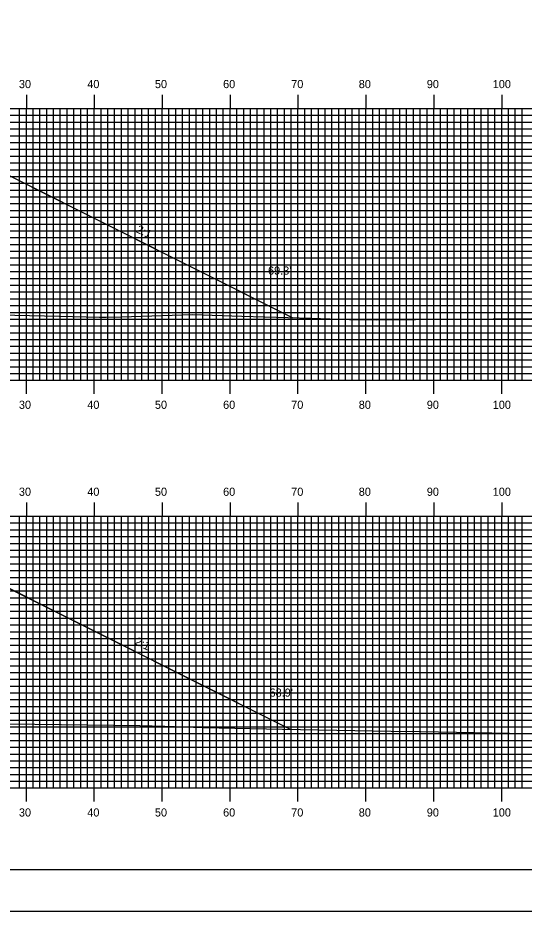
# Model space of a CAD drawing. Extents: x 1810980 to 1811323, y 442591 to 442811.
# Drawn here: x 1811174.6 to 1811249.2, y 442590.5 to 442722 of the extents above; entities that cross this region are included whole.
import ezdxf

# ---------------------------------------------------------------- set-up
doc = ezdxf.new("R2010")
doc.units = 0
for name, color, linetype in [('ANNOTATION', 7, 'Continuous'), ('BORDER', 7, 'Continuous'), ('D_Roadway_Centerline', 7, 'Continuous'), ('D_Roadway_SlopeLines', 7, 'Continuous'), ('D_Text_Standard', 7, 'Continuous'), ('H_V ANNOTATION', 7, 'Continuous'), ('MAJOR', 7, 'Continuous'), ('MINOR', 7, 'Continuous'), ('PLOT BOUNDARY', 7, 'Continuous'), ('S_Roadway_Centerline', 7, 'Continuous')]:
    doc.layers.add(name, color=color, linetype=linetype)

msp = doc.modelspace()

# ---------------------------------------------------------------- linework, layer by layer
at = {"layer": 'BORDER'}
msp.add_lwpolyline([(1810996.29, 442596.67), (1811316.29, 442596.67), (1811316.29, 442806.67), (1810996.29, 442806.67)], close=True, dxfattribs=at)
at = {"layer": 'D_Roadway_Centerline'}
for points in [[(1811076.36, 442679.21), (1811117.68, 442699.87), (1811122.89, 442702.48), (1811125.89, 442702.54), (1811133.89, 442702.7), (1811145.89, 442702.12), (1811157.89, 442701.54), (1811165.89, 442701.16), (1811168.89, 442701.02), (1811174.42, 442698.25), (1811215.15, 442677.88)], [(1811078.22, 442619.39), (1811117.68, 442639.12), (1811122.89, 442641.73), (1811125.89, 442641.79), (1811133.89, 442641.95), (1811145.89, 442641.37), (1811157.89, 442640.79), (1811165.89, 442640.41), (1811168.89, 442640.27), (1811174.42, 442637.5), (1811214.76, 442617.33)]]:
    msp.add_lwpolyline(points, dxfattribs=at)
at = {"layer": 'D_Roadway_SlopeLines'}
for points in [[(1811168.89, 442701.02), (1811215.15, 442677.88)], [(1811168.89, 442640.27), (1811214.76, 442617.33)]]:
    msp.add_lwpolyline(points, dxfattribs=at)
at = {"layer": 'MAJOR'}
for p, q in [((1811175.89, 442710.67), (1811175.89, 442708.67)), ((1811185.89, 442710.67), (1811185.89, 442708.67)), ((1811195.89, 442710.67), (1811195.89, 442708.67)), ((1811205.89, 442710.67), (1811205.89, 442708.67)), ((1811215.89, 442710.67), (1811215.89, 442708.67)), ((1811225.89, 442710.67), (1811225.89, 442708.67)), ((1811235.89, 442710.67), (1811235.89, 442708.67)), ((1811245.89, 442710.67), (1811245.89, 442708.67)), ((1811005.89, 442708.67), (1811285.89, 442708.67)), ((1811005.89, 442708.67), (1811285.89, 442708.67)), ((1811175.89, 442668.67), (1811175.89, 442708.67)), ((1811185.89, 442668.67), (1811185.89, 442708.67)), ((1811195.89, 442668.67), (1811195.89, 442708.67)), ((1811205.89, 442668.67), (1811205.89, 442708.67)), ((1811215.89, 442668.67), (1811215.89, 442708.67)), ((1811225.89, 442668.67), (1811225.89, 442708.67)), ((1811235.89, 442668.67), (1811235.89, 442708.67)), ((1811245.89, 442668.67), (1811245.89, 442708.67)), ((1811005.89, 442703.67), (1811285.89, 442703.67)), ((1811005.89, 442698.67), (1811285.89, 442698.67)), ((1811005.89, 442693.67), (1811285.89, 442693.67)), ((1811005.89, 442688.67), (1811285.89, 442688.67)), ((1811005.89, 442683.67), (1811285.89, 442683.67)), ((1811005.89, 442678.67), (1811285.89, 442678.67)), ((1811005.89, 442673.67), (1811285.89, 442673.67)), ((1811005.89, 442668.67), (1811285.89, 442668.67)), ((1811005.89, 442668.67), (1811285.89, 442668.67)), ((1811175.89, 442666.66), (1811175.89, 442668.67)), ((1811185.89, 442666.66), (1811185.89, 442668.67)), ((1811195.89, 442666.66), (1811195.89, 442668.67)), ((1811205.89, 442666.66), (1811205.89, 442668.67)), ((1811215.89, 442666.66), (1811215.89, 442668.67)), ((1811225.89, 442666.66), (1811225.89, 442668.67)), ((1811235.89, 442666.66), (1811235.89, 442668.67)), ((1811245.89, 442666.66), (1811245.89, 442668.67)), ((1811175.89, 442650.67), (1811175.89, 442648.67)), ((1811185.89, 442650.67), (1811185.89, 442648.67)), ((1811195.89, 442650.67), (1811195.89, 442648.67)), ((1811205.89, 442650.67), (1811205.89, 442648.67)), ((1811215.89, 442650.67), (1811215.89, 442648.67)), ((1811225.89, 442650.67), (1811225.89, 442648.67)), ((1811235.89, 442650.67), (1811235.89, 442648.67)), ((1811245.89, 442650.67), (1811245.89, 442648.67)), ((1811005.89, 442648.67), (1811285.89, 442648.67)), ((1811005.89, 442648.67), (1811285.89, 442648.67)), ((1811175.89, 442608.67), (1811175.89, 442648.67)), ((1811185.89, 442608.67), (1811185.89, 442648.67)), ((1811195.89, 442608.67), (1811195.89, 442648.67)), ((1811205.89, 442608.67), (1811205.89, 442648.67)), ((1811215.89, 442608.67), (1811215.89, 442648.67)), ((1811225.89, 442608.67), (1811225.89, 442648.67)), ((1811235.89, 442608.67), (1811235.89, 442648.67)), ((1811245.89, 442608.67), (1811245.89, 442648.67)), ((1811005.89, 442643.67), (1811285.89, 442643.67)), ((1811005.89, 442638.67), (1811285.89, 442638.67)), ((1811005.89, 442633.67), (1811285.89, 442633.67)), ((1811005.89, 442628.67), (1811285.89, 442628.67)), ((1811005.89, 442623.67), (1811285.89, 442623.67)), ((1811005.89, 442618.67), (1811285.89, 442618.67)), ((1811005.89, 442613.67), (1811285.89, 442613.67)), ((1811005.89, 442608.67), (1811285.89, 442608.67)), ((1811005.89, 442608.67), (1811285.89, 442608.67)), ((1811175.89, 442606.66), (1811175.89, 442608.67)), ((1811185.89, 442606.66), (1811185.89, 442608.67)), ((1811195.89, 442606.66), (1811195.89, 442608.67)), ((1811205.89, 442606.66), (1811205.89, 442608.67)), ((1811215.89, 442606.66), (1811215.89, 442608.67)), ((1811225.89, 442606.66), (1811225.89, 442608.67)), ((1811235.89, 442606.66), (1811235.89, 442608.67)), ((1811245.89, 442606.66), (1811245.89, 442608.67))]:
    msp.add_line(p, q, dxfattribs=at)
at = {"layer": 'MINOR'}
for p, q in [((1811174.89, 442668.67), (1811174.89, 442708.67)), ((1811176.89, 442668.67), (1811176.89, 442708.67)), ((1811177.89, 442668.67), (1811177.89, 442708.67)), ((1811178.89, 442668.67), (1811178.89, 442708.67)), ((1811179.89, 442668.67), (1811179.89, 442708.67)), ((1811180.89, 442668.67), (1811180.89, 442708.67)), ((1811181.89, 442668.67), (1811181.89, 442708.67)), ((1811182.89, 442668.67), (1811182.89, 442708.67)), ((1811183.89, 442668.67), (1811183.89, 442708.67)), ((1811184.89, 442668.67), (1811184.89, 442708.67)), ((1811186.89, 442668.67), (1811186.89, 442708.67)), ((1811187.89, 442668.67), (1811187.89, 442708.67)), ((1811188.89, 442668.67), (1811188.89, 442708.67)), ((1811189.89, 442668.67), (1811189.89, 442708.67)), ((1811190.89, 442668.67), (1811190.89, 442708.67)), ((1811191.89, 442668.67), (1811191.89, 442708.67)), ((1811192.89, 442668.67), (1811192.89, 442708.67)), ((1811193.89, 442668.67), (1811193.89, 442708.67)), ((1811194.89, 442668.67), (1811194.89, 442708.67)), ((1811196.89, 442668.67), (1811196.89, 442708.67)), ((1811197.89, 442668.67), (1811197.89, 442708.67)), ((1811198.89, 442668.67), (1811198.89, 442708.67)), ((1811199.89, 442668.67), (1811199.89, 442708.67)), ((1811200.89, 442668.67), (1811200.89, 442708.67)), ((1811201.89, 442668.67), (1811201.89, 442708.67)), ((1811202.89, 442668.67), (1811202.89, 442708.67)), ((1811203.89, 442668.67), (1811203.89, 442708.67)), ((1811204.89, 442668.67), (1811204.89, 442708.67)), ((1811206.89, 442668.67), (1811206.89, 442708.67)), ((1811207.89, 442668.67), (1811207.89, 442708.67)), ((1811208.89, 442668.67), (1811208.89, 442708.67)), ((1811209.89, 442668.67), (1811209.89, 442708.67)), ((1811210.89, 442668.67), (1811210.89, 442708.67)), ((1811211.89, 442668.67), (1811211.89, 442708.67)), ((1811212.89, 442668.67), (1811212.89, 442708.67)), ((1811213.89, 442668.67), (1811213.89, 442708.67)), ((1811214.89, 442668.67), (1811214.89, 442708.67)), ((1811216.89, 442668.67), (1811216.89, 442708.67)), ((1811217.89, 442668.67), (1811217.89, 442708.67)), ((1811218.89, 442668.67), (1811218.89, 442708.67)), ((1811219.89, 442668.67), (1811219.89, 442708.67)), ((1811220.89, 442668.67), (1811220.89, 442708.67)), ((1811221.89, 442668.67), (1811221.89, 442708.67)), ((1811222.89, 442668.67), (1811222.89, 442708.67)), ((1811223.89, 442668.67), (1811223.89, 442708.67)), ((1811224.89, 442668.67), (1811224.89, 442708.67)), ((1811226.89, 442668.67), (1811226.89, 442708.67)), ((1811227.89, 442668.67), (1811227.89, 442708.67)), ((1811228.89, 442668.67), (1811228.89, 442708.67)), ((1811229.89, 442668.67), (1811229.89, 442708.67)), ((1811230.89, 442668.67), (1811230.89, 442708.67)), ((1811231.89, 442668.67), (1811231.89, 442708.67)), ((1811232.89, 442668.67), (1811232.89, 442708.67)), ((1811233.89, 442668.67), (1811233.89, 442708.67)), ((1811234.89, 442668.67), (1811234.89, 442708.67)), ((1811236.89, 442668.67), (1811236.89, 442708.67)), ((1811237.89, 442668.67), (1811237.89, 442708.67)), ((1811238.89, 442668.67), (1811238.89, 442708.67)), ((1811239.89, 442668.67), (1811239.89, 442708.67)), ((1811240.89, 442668.67), (1811240.89, 442708.67)), ((1811241.89, 442668.67), (1811241.89, 442708.67)), ((1811242.89, 442668.67), (1811242.89, 442708.67)), ((1811243.89, 442668.67), (1811243.89, 442708.67)), ((1811244.89, 442668.67), (1811244.89, 442708.67)), ((1811246.89, 442668.67), (1811246.89, 442708.67)), ((1811247.89, 442668.67), (1811247.89, 442708.67)), ((1811248.89, 442668.67), (1811248.89, 442708.67)), ((1811005.89, 442707.67), (1811285.89, 442707.67)), ((1811005.89, 442706.67), (1811285.89, 442706.67)), ((1811005.89, 442705.67), (1811285.89, 442705.67)), ((1811005.89, 442704.67), (1811285.89, 442704.67)), ((1811005.89, 442702.67), (1811285.89, 442702.67)), ((1811005.89, 442701.67), (1811285.89, 442701.67)), ((1811005.89, 442700.67), (1811285.89, 442700.67)), ((1811005.89, 442699.67), (1811285.89, 442699.67)), ((1811005.89, 442697.67), (1811285.89, 442697.67)), ((1811005.89, 442696.67), (1811285.89, 442696.67)), ((1811005.89, 442695.67), (1811285.89, 442695.67)), ((1811005.89, 442694.67), (1811285.89, 442694.67)), ((1811005.89, 442692.67), (1811285.89, 442692.67)), ((1811005.89, 442691.67), (1811285.89, 442691.67)), ((1811005.89, 442690.67), (1811285.89, 442690.67)), ((1811005.89, 442689.67), (1811285.89, 442689.67)), ((1811005.89, 442687.67), (1811285.89, 442687.67)), ((1811005.89, 442686.67), (1811285.89, 442686.67)), ((1811005.89, 442685.67), (1811285.89, 442685.67)), ((1811005.89, 442684.67), (1811285.89, 442684.67)), ((1811005.89, 442682.67), (1811285.89, 442682.67)), ((1811005.89, 442681.67), (1811285.89, 442681.67)), ((1811005.89, 442680.67), (1811285.89, 442680.67)), ((1811005.89, 442679.67), (1811285.89, 442679.67)), ((1811005.89, 442677.67), (1811285.89, 442677.67)), ((1811005.89, 442676.67), (1811285.89, 442676.67)), ((1811005.89, 442675.67), (1811285.89, 442675.67)), ((1811005.89, 442674.67), (1811285.89, 442674.67)), ((1811005.89, 442672.67), (1811285.89, 442672.67)), ((1811005.89, 442671.67), (1811285.89, 442671.67)), ((1811005.89, 442670.67), (1811285.89, 442670.67)), ((1811005.89, 442669.67), (1811285.89, 442669.67)), ((1811005.89, 442647.67), (1811285.89, 442647.67)), ((1811174.89, 442608.67), (1811174.89, 442648.67)), ((1811176.89, 442608.67), (1811176.89, 442648.67)), ((1811177.89, 442608.67), (1811177.89, 442648.67)), ((1811178.89, 442608.67), (1811178.89, 442648.67)), ((1811179.89, 442608.67), (1811179.89, 442648.67)), ((1811180.89, 442608.67), (1811180.89, 442648.67)), ((1811181.89, 442608.67), (1811181.89, 442648.67)), ((1811182.89, 442608.67), (1811182.89, 442648.67)), ((1811183.89, 442608.67), (1811183.89, 442648.67)), ((1811184.89, 442608.67), (1811184.89, 442648.67)), ((1811186.89, 442608.67), (1811186.89, 442648.67)), ((1811187.89, 442608.67), (1811187.89, 442648.67)), ((1811188.89, 442608.67), (1811188.89, 442648.67)), ((1811189.89, 442608.67), (1811189.89, 442648.67)), ((1811190.89, 442608.67), (1811190.89, 442648.67)), ((1811191.89, 442608.67), (1811191.89, 442648.67)), ((1811192.89, 442608.67), (1811192.89, 442648.67)), ((1811193.89, 442608.67), (1811193.89, 442648.67)), ((1811194.89, 442608.67), (1811194.89, 442648.67)), ((1811196.89, 442608.67), (1811196.89, 442648.67)), ((1811197.89, 442608.67), (1811197.89, 442648.67)), ((1811198.89, 442608.67), (1811198.89, 442648.67)), ((1811199.89, 442608.67), (1811199.89, 442648.67)), ((1811200.89, 442608.67), (1811200.89, 442648.67)), ((1811201.89, 442608.67), (1811201.89, 442648.67)), ((1811202.89, 442608.67), (1811202.89, 442648.67)), ((1811203.89, 442608.67), (1811203.89, 442648.67)), ((1811204.89, 442608.67), (1811204.89, 442648.67)), ((1811206.89, 442608.67), (1811206.89, 442648.67)), ((1811207.89, 442608.67), (1811207.89, 442648.67)), ((1811208.89, 442608.67), (1811208.89, 442648.67)), ((1811209.89, 442608.67), (1811209.89, 442648.67)), ((1811210.89, 442608.67), (1811210.89, 442648.67)), ((1811211.89, 442608.67), (1811211.89, 442648.67)), ((1811212.89, 442608.67), (1811212.89, 442648.67)), ((1811213.89, 442608.67), (1811213.89, 442648.67)), ((1811214.89, 442608.67), (1811214.89, 442648.67)), ((1811216.89, 442608.67), (1811216.89, 442648.67)), ((1811217.89, 442608.67), (1811217.89, 442648.67)), ((1811218.89, 442608.67), (1811218.89, 442648.67)), ((1811219.89, 442608.67), (1811219.89, 442648.67)), ((1811220.89, 442608.67), (1811220.89, 442648.67)), ((1811221.89, 442608.67), (1811221.89, 442648.67)), ((1811222.89, 442608.67), (1811222.89, 442648.67)), ((1811223.89, 442608.67), (1811223.89, 442648.67)), ((1811224.89, 442608.67), (1811224.89, 442648.67)), ((1811226.89, 442608.67), (1811226.89, 442648.67)), ((1811227.89, 442608.67), (1811227.89, 442648.67)), ((1811228.89, 442608.67), (1811228.89, 442648.67)), ((1811229.89, 442608.67), (1811229.89, 442648.67)), ((1811230.89, 442608.67), (1811230.89, 442648.67)), ((1811231.89, 442608.67), (1811231.89, 442648.67)), ((1811232.89, 442608.67), (1811232.89, 442648.67)), ((1811233.89, 442608.67), (1811233.89, 442648.67)), ((1811234.89, 442608.67), (1811234.89, 442648.67)), ((1811236.89, 442608.67), (1811236.89, 442648.67)), ((1811237.89, 442608.67), (1811237.89, 442648.67)), ((1811238.89, 442608.67), (1811238.89, 442648.67)), ((1811239.89, 442608.67), (1811239.89, 442648.67)), ((1811240.89, 442608.67), (1811240.89, 442648.67)), ((1811241.89, 442608.67), (1811241.89, 442648.67)), ((1811242.89, 442608.67), (1811242.89, 442648.67)), ((1811243.89, 442608.67), (1811243.89, 442648.67)), ((1811244.89, 442608.67), (1811244.89, 442648.67)), ((1811246.89, 442608.67), (1811246.89, 442648.67)), ((1811247.89, 442608.67), (1811247.89, 442648.67)), ((1811248.89, 442608.67), (1811248.89, 442648.67)), ((1811005.89, 442646.67), (1811285.89, 442646.67)), ((1811005.89, 442645.67), (1811285.89, 442645.67)), ((1811005.89, 442644.67), (1811285.89, 442644.67)), ((1811005.89, 442642.67), (1811285.89, 442642.67)), ((1811005.89, 442641.67), (1811285.89, 442641.67)), ((1811005.89, 442640.67), (1811285.89, 442640.67)), ((1811005.89, 442639.67), (1811285.89, 442639.67)), ((1811005.89, 442637.67), (1811285.89, 442637.67)), ((1811005.89, 442636.67), (1811285.89, 442636.67)), ((1811005.89, 442635.67), (1811285.89, 442635.67)), ((1811005.89, 442634.67), (1811285.89, 442634.67)), ((1811005.89, 442632.67), (1811285.89, 442632.67)), ((1811005.89, 442631.67), (1811285.89, 442631.67)), ((1811005.89, 442630.67), (1811285.89, 442630.67)), ((1811005.89, 442629.67), (1811285.89, 442629.67)), ((1811005.89, 442627.67), (1811285.89, 442627.67)), ((1811005.89, 442626.67), (1811285.89, 442626.67)), ((1811005.89, 442625.67), (1811285.89, 442625.67)), ((1811005.89, 442624.67), (1811285.89, 442624.67)), ((1811005.89, 442622.67), (1811285.89, 442622.67)), ((1811005.89, 442621.67), (1811285.89, 442621.67)), ((1811005.89, 442620.67), (1811285.89, 442620.67)), ((1811005.89, 442619.67), (1811285.89, 442619.67)), ((1811005.89, 442617.67), (1811285.89, 442617.67)), ((1811005.89, 442616.67), (1811285.89, 442616.67)), ((1811005.89, 442615.67), (1811285.89, 442615.67)), ((1811005.89, 442614.67), (1811285.89, 442614.67)), ((1811005.89, 442612.67), (1811285.89, 442612.67)), ((1811005.89, 442611.67), (1811285.89, 442611.67)), ((1811005.89, 442610.67), (1811285.89, 442610.67)), ((1811005.89, 442609.67), (1811285.89, 442609.67))]:
    msp.add_line(p, q, dxfattribs=at)
at = {"layer": 'PLOT BOUNDARY'}
msp.add_lwpolyline([(1810980.1, 442590.55), (1811320.1, 442590.55), (1811320.1, 442810.55), (1810980.1, 442810.55)], close=True, dxfattribs=at)
at = {"layer": 'S_Roadway_Centerline'}
for points in [[(1811167.63, 442678.4), (1811180.71, 442678.13), (1811186.64, 442677.97), (1811187.66, 442677.97), (1811189.85, 442677.99), (1811200.35, 442678.35), (1811207.61, 442678.11), (1811217.8, 442677.8), (1811223.46, 442677.62), (1811227.5, 442677.57), (1811250.31, 442677.78), (1811255.91, 442677.81), (1811256.5, 442677.81), (1811257.39, 442677.79), (1811274.31, 442677.46), (1811279.78, 442677.33), (1811285.89, 442677.14)], [(1811173.27, 442618.12), (1811192.61, 442617.86), (1811196.26, 442617.76), (1811201.92, 442617.56), (1811213.61, 442617.35), (1811229.63, 442617.02), (1811233.98, 442616.96), (1811252.28, 442616.64), (1811254.46, 442616.6), (1811255.04, 442616.59), (1811274.55, 442616.79), (1811284.49, 442616.68), (1811285.89, 442616.62)]]:
    msp.add_lwpolyline(points, dxfattribs=at)

# ---------------------------------------------------------------- texts
at = {"layer": 'ANNOTATION'}
for p in [(1811191.96, 442690.52), (1811191.76, 442629.87)]:
    msp.add_text('2:1', height=1.2, rotation=333.4349, dxfattribs=at).set_placement(p)
at = {"layer": 'D_Text_Standard'}
for s, p in [("69.3'", (1811211.48, 442684.22)), ("68.9'", (1811211.7, 442622.11))]:
    msp.add_text(s, height=1.2, dxfattribs=at).set_placement(p)
at = {"layer": 'H_V ANNOTATION'}
for s, p in [('30', (1811174.79, 442711.67)), ('40', (1811184.86, 442711.67)), ('50', (1811194.82, 442711.67)), ('60', (1811204.86, 442711.67)), ('70', (1811214.89, 442711.67)), ('80', (1811224.84, 442711.67)), ('90', (1811234.86, 442711.67)), ('100', (1811244.57, 442711.67)), ('30', (1811174.79, 442664.47)), ('40', (1811184.86, 442664.47)), ('50', (1811194.82, 442664.47)), ('60', (1811204.86, 442664.47)), ('70', (1811214.89, 442664.47)), ('80', (1811224.84, 442664.47)), ('90', (1811234.86, 442664.47)), ('100', (1811244.57, 442664.47)), ('30', (1811174.79, 442651.67)), ('40', (1811184.86, 442651.67)), ('50', (1811194.82, 442651.67)), ('60', (1811204.86, 442651.67)), ('70', (1811214.89, 442651.67)), ('80', (1811224.84, 442651.67)), ('90', (1811234.86, 442651.67)), ('100', (1811244.57, 442651.67)), ('30', (1811174.79, 442604.47)), ('40', (1811184.86, 442604.47)), ('50', (1811194.82, 442604.47)), ('60', (1811204.86, 442604.47)), ('70', (1811214.89, 442604.47)), ('80', (1811224.84, 442604.47)), ('90', (1811234.86, 442604.47)), ('100', (1811244.57, 442604.47))]:
    msp.add_text(s, height=1.2, dxfattribs=at).set_placement(p)

doc.saveas('drawing.dxf')
